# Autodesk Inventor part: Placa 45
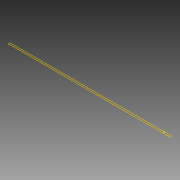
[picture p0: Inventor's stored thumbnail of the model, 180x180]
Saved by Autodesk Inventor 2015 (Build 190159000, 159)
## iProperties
Created: 2015-04
Part Number: Placa 45
Material: Generic
Document SubType Name: Modeling
Designer: suporte
Density: 1 g/cm^3
Appearance: Default
Author: suporte
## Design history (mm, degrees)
workplane "Work Plane1"
sketch "Sketch1"
  geometry: L1 (-1106.156, 0)-(0, 0) reference; L2 (-506.393, 2000)-(-506.393, -100) reference; L3 (-506.393, -100)-(-1106.156, -100); L4 (-1106.156, -100)-(-1106.156, 0); L5 (-1106.156, 0)-(-506.393, 0); L6 (-506.393, 0)-(-506.393, -100); L7 (-506.393, -100)-(-1106.156, -100); L8 (-1106.156, -100)-(-1106.156, -112.5); L9 (-1106.156, -112.5)-(-506.393, -112.5); L10 (-506.393, -112.5)-(-506.393, -100)
  constraints: 16 end point, 4 parallel, 2 horizontal, 2 perpendicular, 1 point on line
  dimensions: "d2" = 12.5 distance of L8.end L7.end
extrude "Extrusion1" new body sketch "Sketch1" distance "d0" = 12.5; taper "d1" = 0 deg
body "Solid1"
node "Reference1"
node "Reference2"
